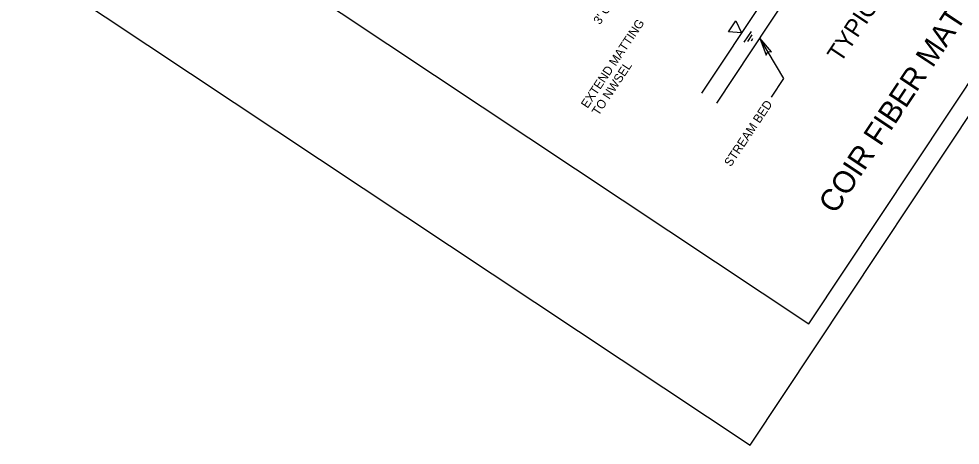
# Model space of a CAD drawing. Extents: x 561231 to 564240, y 590260 to 602519.
# Drawn here: x 563134 to 563838, y 590260 to 590579 of the extents above; entities that cross this region are included whole.
import ezdxf

# ---------------------------------------------------------------- set-up
doc = ezdxf.new("R2010")
doc.units = 0
for name, color, linetype in [('Old_Level_1', 7, 'Continuous'), ('Old_Level_2', 7, 'Continuous'), ('Scratch_Level_0', 7, 'Continuous'), ('Sheet Plot Border Outside CELL', 7, 'Continuous')]:
    doc.layers.add(name, color=color, linetype=linetype)

# ---------------------------------------------------------------- blocks, each defined once
blk = doc.blocks.new('TERM')
at = {"layer": 'Old_Level_2'}
blk.add_lwpolyline([(-27, 4.65), (0, 0), (-27.15, -4.8), (-23.7, 0)], close=True, dxfattribs=at)

msp = doc.modelspace()

# ---------------------------------------------------------------- linework, layer by layer
at = {"layer": 'Old_Level_1'}
for p, q in [((563645.21, 590522.98), (563707.36, 590616.53)), ((563656.3, 590515.62), (563709.09, 590595.08)), ((563676.79, 590561.08), (563682.23, 590569.26)), ((563679.52, 590561.62), (563682.78, 590566.54)), ((563682.24, 590562.17), (563683.33, 590563.81)), ((563706.52, 590534.02), (563688.55, 590564.17)), ((563697.15, 590519.92), (563706.52, 590534.02)), ((563725.27, 590350.42), (563725.27, 590350.42))]:
    msp.add_line(p, q, dxfattribs=at)
for points in [[(563698.59, 591448.69), (563200.53, 590699.06), (563725.27, 590350.42), (564223.33, 591100.04)], [(563665.06, 590568.87), (563670.5, 590577.05), (563674.87, 590568.25)]]:
    msp.add_lwpolyline(points, close=True, dxfattribs=at)
at = {"layer": 'Scratch_Level_0'}
msp.add_line((563681.23, 590259.74), (563681.23, 590259.74), dxfattribs=at)
at = {"layer": 'Sheet Plot Border Outside CELL'}
msp.add_lwpolyline([(563681.23, 590259.74), (564240.22, 591101.07), (563692.99, 591464.65), (563134, 590623.32)], close=True, dxfattribs=at)

# ---------------------------------------------------------------- block references
at = {"layer": 'Old_Level_1', "xscale": 0.49132800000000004, "yscale": -0.4913280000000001, "rotation": 120.78209553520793}
msp.add_blockref('TERM', (563688.57, 590564.18), dxfattribs=at)

# ---------------------------------------------------------------- texts
at = {"layer": 'Old_Level_1'}
for s, height, rotation, p in [('TYPICAL CROSS SECTION', 13.102, 56.39933, (563749.01, 590545.12)), ('COIR FIBER MATTING DETAIL', 16.3776, 56.39933, (563745.07, 590431.91)), ("3' CENTERS", 6.551, 56.39933, (563568.9, 590573.79)), ('EXTEND MATTING', 6.5511, 56.39933, (563559.61, 590511.2)), ('TO NWSEL', 6.551, 56.39933, (563567.8, 590505.74)), ('STREAM BED', 6.551, 56.39964, (563666.81, 590467.54))]:
    msp.add_text(s, height=height, rotation=rotation, dxfattribs=at).set_placement(p)

doc.saveas('drawing.dxf')
